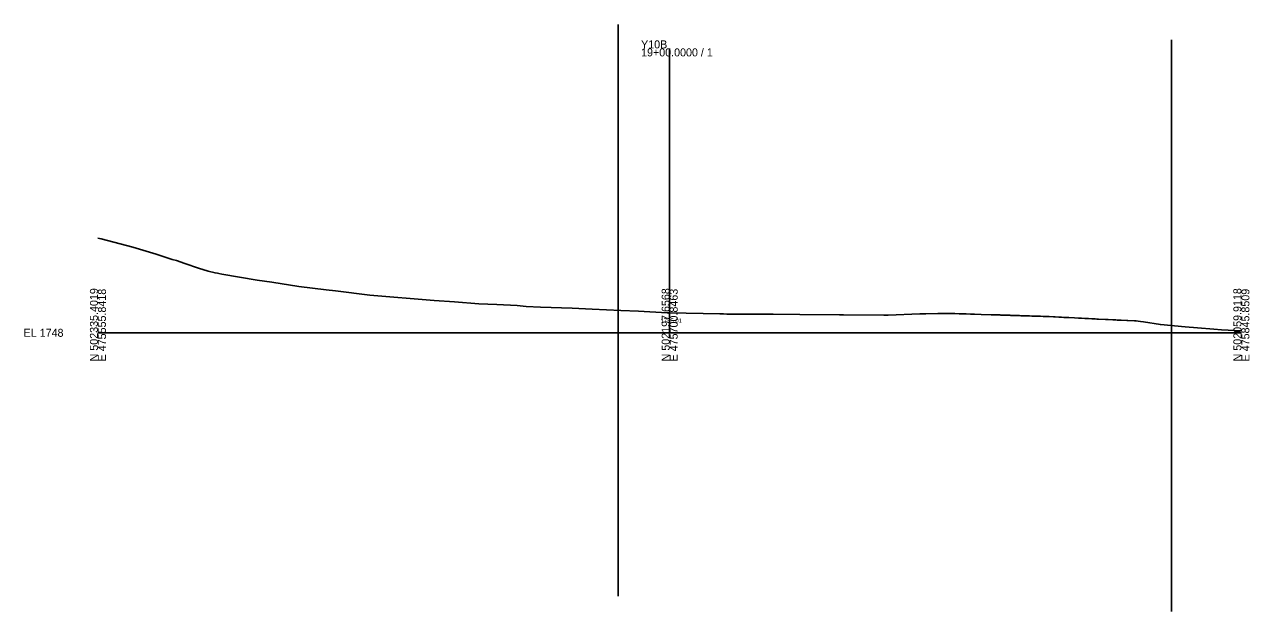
# Model space of a CAD drawing. Extents: x -26 to 1803, y -10 to 9558.
# Drawn here: x -25.7 to 402.8, y 8902.5 to 9107.8 of the extents above; entities that cross this region are included whole.
import ezdxf

# ---------------------------------------------------------------- set-up
doc = ezdxf.new("R2010")
doc.units = 0
for name, color, linetype in [('Exist Cross Section Cell', 7, 'Continuous'), ('Exist XS Center Line Elevation Label', 7, 'Continuous'), ('Exist XS Ground Line', 7, 'Continuous'), ('Scratch_Level_2', 7, 'Continuous')]:
    doc.layers.add(name, color=color, linetype=linetype)

msp = doc.modelspace()

# ---------------------------------------------------------------- linework, layer by layer
at = {"layer": 'Exist Cross Section Cell'}
for p, q in [((200, 9000), (200, 9099.49)), ((0, 9000), (200, 9000)), ((200, 9000), (400, 9000))]:
    msp.add_line(p, q, dxfattribs=at)
at = {"layer": 'Exist XS Ground Line'}
msp.add_lwpolyline([(0, 9033.16), (1.08, 9032.88), (12.17, 9029.95), (14.49, 9029.21), (20.37, 9027.51), (25.96, 9025.65), (27.45, 9025.26), (30.42, 9024.26), (35.12, 9022.63), (38.54, 9021.56), (40.98, 9020.95), (41.87, 9020.82), (42.34, 9020.72), (43.36, 9020.53), (55.7, 9018.41), (60.8, 9017.68), (70.31, 9016.18), (79.8, 9015.02), (83.13, 9014.63), (95.1, 9013.17), (117.6, 9011.35), (124.7, 9010.82), (133.29, 9010.18), (139.55, 9009.89), (146.67, 9009.51), (149.8, 9009.26), (154.81, 9008.97), (165.92, 9008.63), (172.84, 9008.26), (182.92, 9007.8), (189.1, 9007.55), (199.09, 9007.03), (200, 9007.01), (217.55, 9006.62), (218.81, 9006.59), (220.03, 9006.57), (225.13, 9006.58), (233.11, 9006.56), (236.24, 9006.49), (245.53, 9006.42), (259.39, 9006.24), (260.83, 9006.28), (274.96, 9006.15), (276.47, 9006.2), (287.48, 9006.66), (289.62, 9006.69), (293.83, 9006.74), (295.34, 9006.75), (297.58, 9006.79), (298.79, 9006.76), (299.76, 9006.73), (301.24, 9006.68), (301.77, 9006.67), (302.35, 9006.65), (303.77, 9006.61), (305.26, 9006.55), (306.6, 9006.52), (308.92, 9006.44), (312.49, 9006.33), (314.06, 9006.28), (315.53, 9006.24), (315.83, 9006.23), (316.15, 9006.22), (318.98, 9006.12), (319.35, 9006.11), (319.75, 9006.09), (321.12, 9006.05), (322.42, 9006), (322.9, 9005.99), (323.41, 9005.97), (324.68, 9005.94), (325.87, 9005.9), (326.66, 9005.87), (328.12, 9005.83), (329.28, 9005.8), (329.7, 9005.79), (330.69, 9005.76), (331.8, 9005.7), (332.75, 9005.66), (334.3, 9005.58), (334.81, 9005.55), (336.18, 9005.48), (337.03, 9005.44), (337.92, 9005.39), (338.81, 9005.35), (339.63, 9005.3), (341.57, 9005.21), (343.07, 9005.13), (344.11, 9005.08), (345.2, 9005.03), (346.53, 9004.97), (347.65, 9004.91), (348.85, 9004.85), (349.42, 9004.82), (349.96, 9004.8), (352.47, 9004.68), (353.42, 9004.63), (354.98, 9004.56), (356.11, 9004.5), (356.5, 9004.48), (356.87, 9004.46), (357.63, 9004.43), (357.96, 9004.41), (359.98, 9004.31), (360.31, 9004.3), (362.63, 9004.18), (363.23, 9004.15), (363.94, 9004.11), (364.75, 9004.01), (365.74, 9003.88), (371.67, 9002.88), (380.28, 9002.08), (384.65, 9001.73), (390.4, 9001.22), (393.08, 9000.99), (400, 9000.67)], dxfattribs=at)
at = {"layer": 'Scratch_Level_2'}
for p, q in [((181.94, 9107.85), (181.94, 8907.85)), ((375.57, 9102.52), (375.57, 8902.52))]:
    msp.add_line(p, q, dxfattribs=at)

# ---------------------------------------------------------------- texts
at = {"layer": 'Exist Cross Section Cell'}
for s, p in [('Y10B', (190, 9099.49)), ('19+00.0000 / 1', (190, 9096.69)), ('EL 1748', (-26, 8998.6))]:
    msp.add_text(s, height=2.8, dxfattribs=at).set_placement(p)
for s, p in [('N 502335.4019', (0, 8990)), ('E 475555.8418', (2.8, 8990)), ('N 502197.6568', (200, 8990)), ('E 475700.8463', (202.8, 8990)), ('N 502059.9118', (400, 8990)), ('E 475845.8509', (402.8, 8990))]:
    msp.add_text(s, height=2.8, rotation=90, dxfattribs=at).set_placement(p)
at = {"layer": 'Exist XS Center Line Elevation Label'}
msp.add_text('1755.01', height=1.5, dxfattribs=at).set_placement((196.81, 9003.51))

doc.saveas('drawing.dxf')
